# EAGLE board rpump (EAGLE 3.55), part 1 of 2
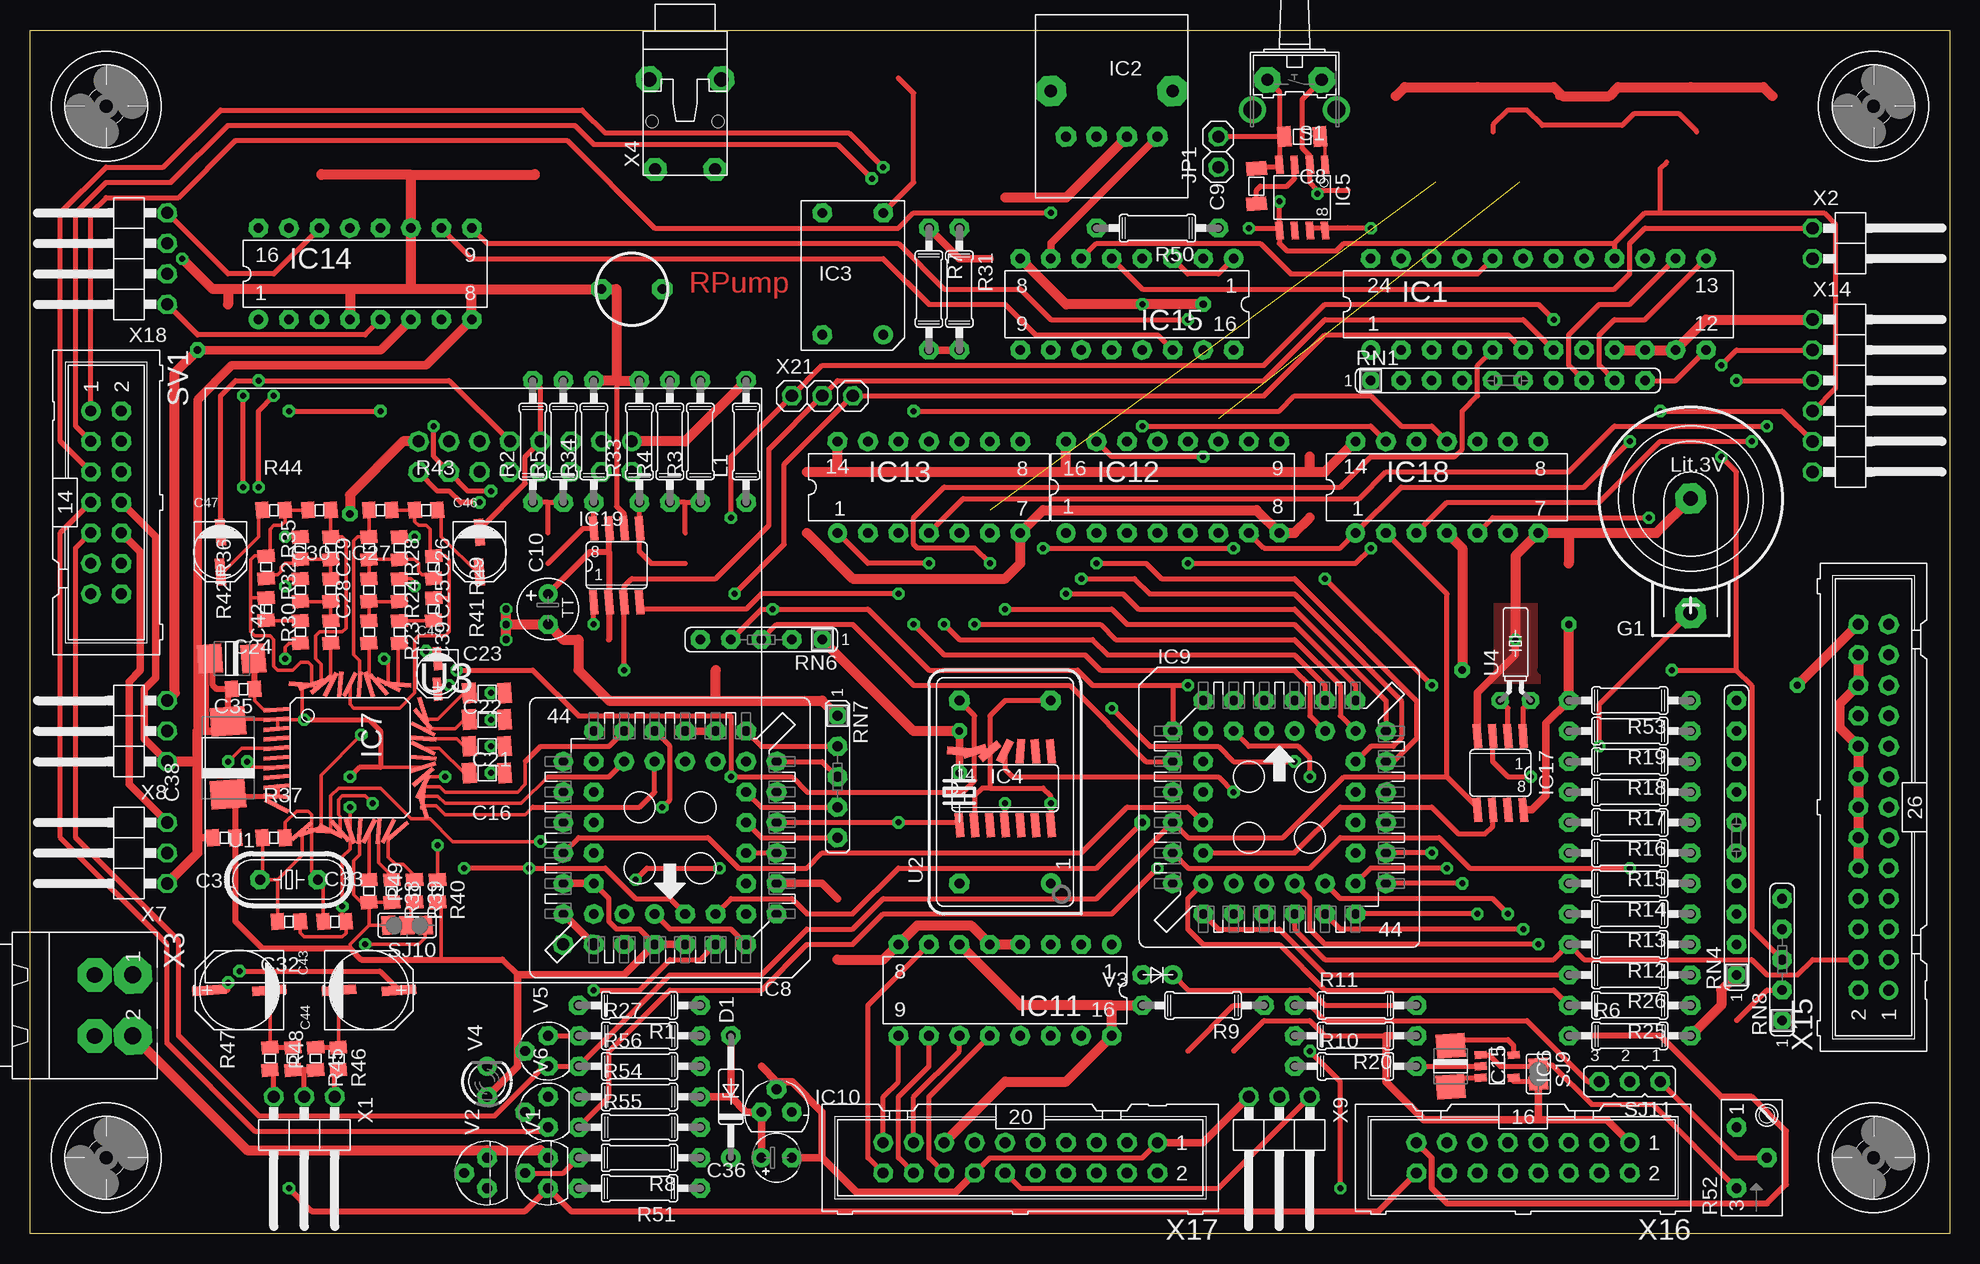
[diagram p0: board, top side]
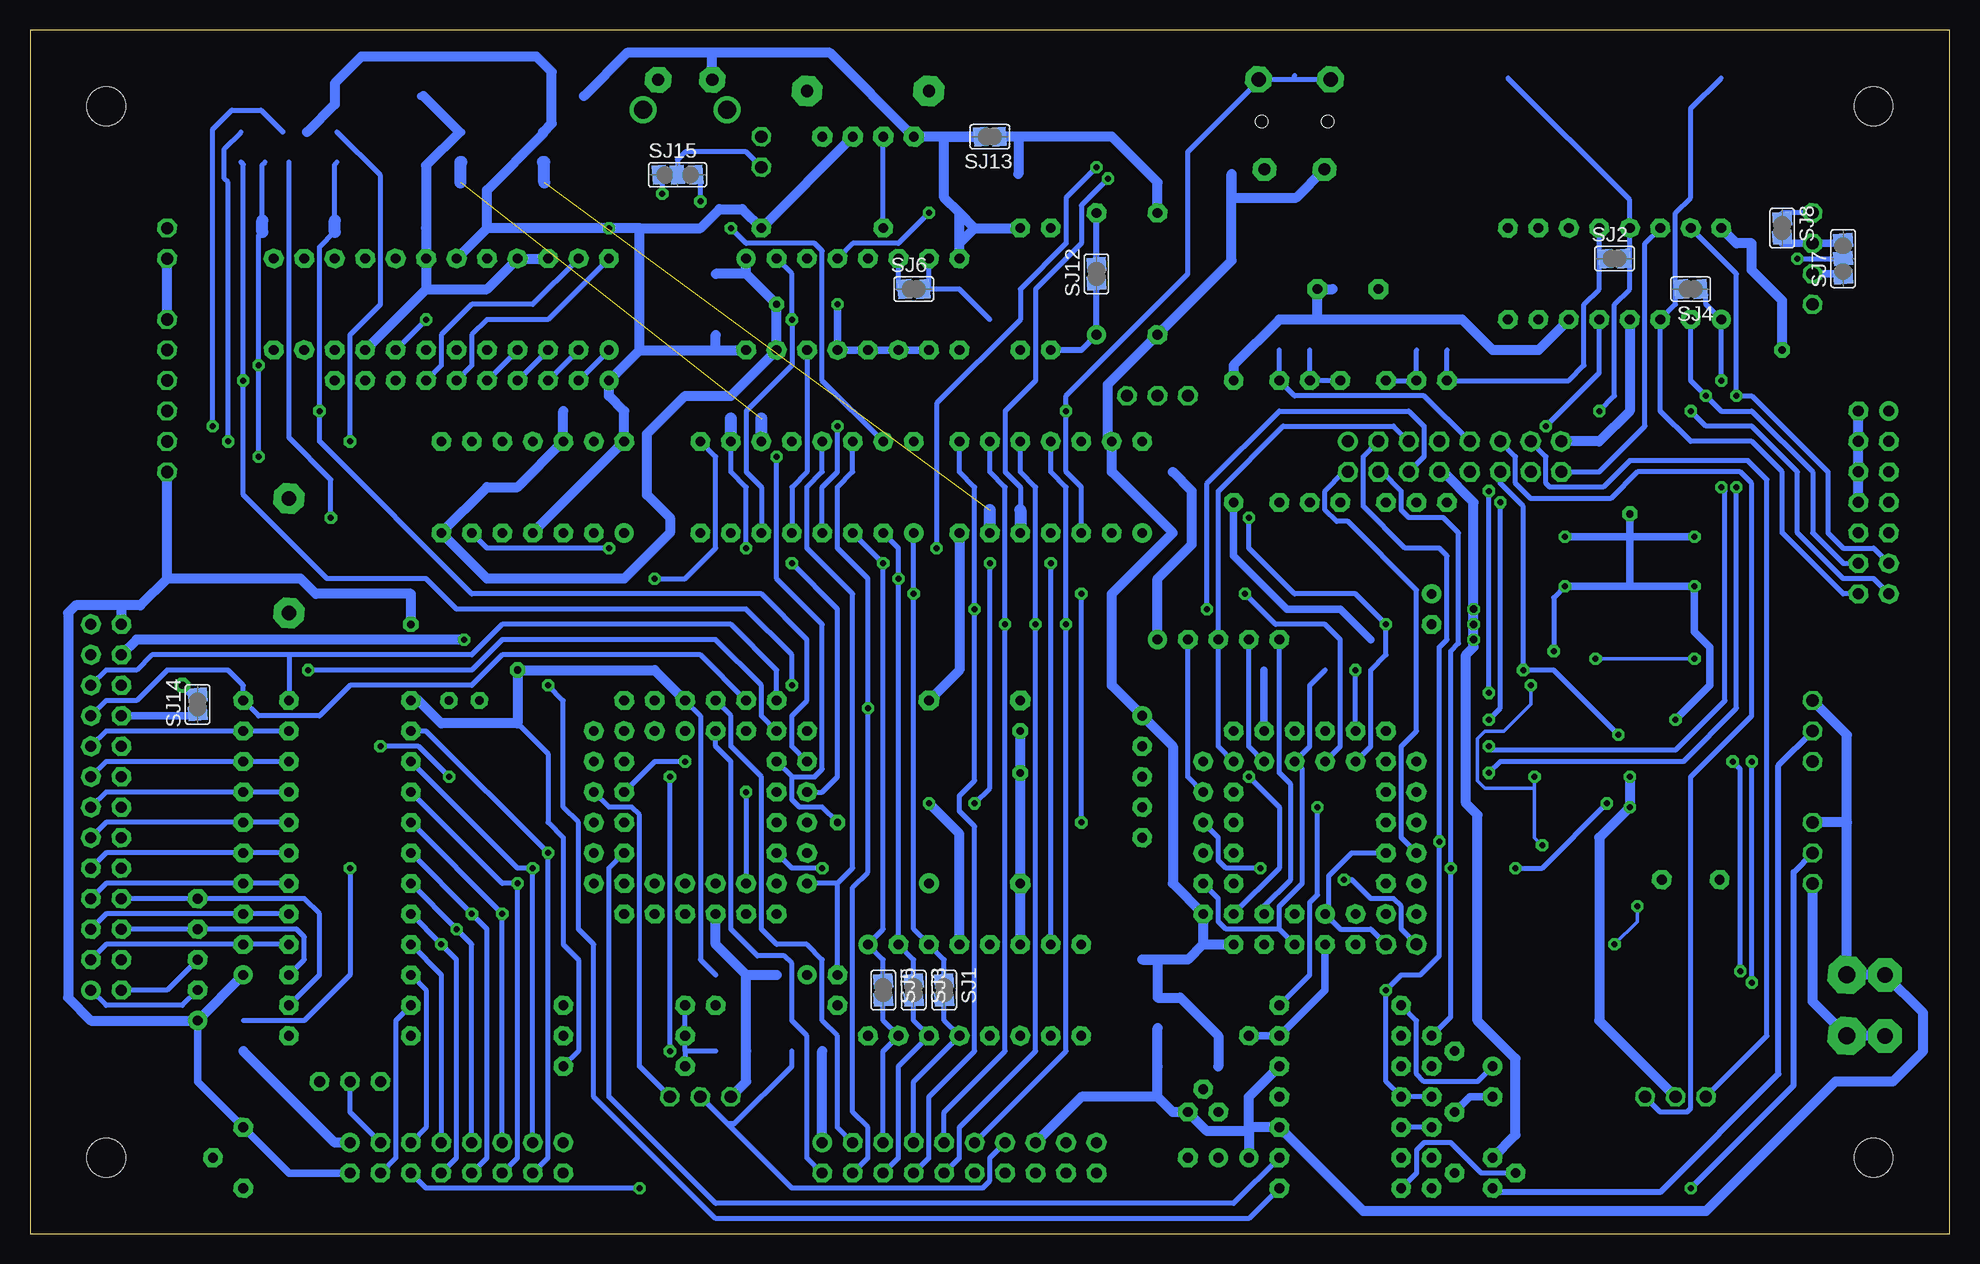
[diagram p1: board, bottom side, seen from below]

Size 160.02 x 100.33 mm. Coordinates in mm from the lower left corner, seen from the top.
Outline: 0,0 0,100.33 160.02,100.33 160.02,0 0,0
Copper layers used: Top, Bottom
tRestrict: 4 lines

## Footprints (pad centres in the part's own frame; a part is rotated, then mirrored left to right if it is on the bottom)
06 = smd 1.143 x 1.702 rotated 4.4:  1.473,0 | smd 1.143 x 1.702 rotated 4.3:  -1.473,0
2D5 = drill 0.813 pad 1.6 octagon:  -1.27,0 | drill 0.813 pad 1.6 round:  1.27,0
28 = smd 2.007 x 2.388 rotated 4.4:  1.702,0 | smd 2.007 x 2.388 rotated 4.3:  -1.702,0
05 = smd 1.092 x 1.397 rotated 4.4:  0.94,0 | smd 1.092 x 1.397 rotated 4.3:  -0.94,0
28' = smd 2.007 x 2.388 rotated 4.4:  1.802,0 | smd 2.007 x 2.388 rotated 4.3:  -1.802,0
2D4 = drill 0.813 pad 1.6 octagon:  -1.27,0 | drill 0.813 pad 1.6 round:  1.27,0
43 = smd 2.388 x 2.896 rotated 4.4:  3.048,0 | smd 2.388 x 2.896 rotated 4.3:  -3.048,0
C-D = smd 0.8 x 2.85 rotated 4.4:  0,2.5 | smd 0.8 x 2.85 rotated 4.3:  0,-2.5
C-A = smd 0.7 x 1.95 rotated 4.4:  0,1.27 | smd 0.7 x 1.95 rotated 4.3:  0,-1.27
C-B = smd 0.8 x 2.25 rotated 4.4:  0,1.64 | smd 0.8 x 2.25 rotated 4.3:  0,-1.67
35Z10 = drill 0.813 pad 1.6 round:  -5.08,0 | drill 0.813 pad 1.6 octagon:  5.08,0
1216 = drill 1.2 pad 2.54 octagon:  0,9.525;  0,0
L24-3 = drill 0.813 pad 1.6 round:  -13.97,-3.81 | drill 0.813 pad 1.6 octagon:  -11.43,-3.81;  -8.89,-3.81;  -6.35,-3.81;  -3.81,-3.81;  -1.27,-3.81;  1.27,-3.81;  3.81,-3.81;  6.35,-3.81;  8.89,-3.81;  11.43,-3.81;  13.97,-3.81;  13.97,3.81;  11.43,3.81;  8.89,3.81;  6.35,3.81;  3.81,3.81;  1.27,3.81;  -1.27,3.81;  -3.81,3.81;  -6.35,3.81;  -8.89,3.81;  -11.43,3.81;  -13.97,3.81
TX173 = drill 0.813 pad 1.676 octagon:  1.27,3.81;  3.81,3.81;  6.35,3.81;  8.89,3.81 | drill 1.016 pad 2.54 octagon:  0,0;  10.16,0
12545 = drill 0.813 pad 1.6 round:  2.54,-5.08 | drill 0.813 pad 1.6 octagon:  -2.54,-5.08;  2.54,5.08;  -2.54,5.08
14 = smd 0.66 x 2.032 rotated 4.3:  -3.81,-3.073;  1.27,3.073 | smd 0.66 x 2.032 rotated 94.3:  -3.81,3.073 | smd 0.66 x 2.032 rotated 4.4:  -2.54,-3.073 | smd 0.66 x 2.032 rotated 4.5:  -1.27,-3.073 | smd 0.66 x 2.032 rotated 71.8:  -2.54,3.073 | smd 0.66 x 2.032 rotated 49.3:  -1.27,3.073 | smd 0.66 x 2.032 rotated 4.6:  0,-3.073 | smd 0.66 x 2.032 rotated 26.8:  0,3.073 | smd 0.66 x 2.032 rotated 4.7:  1.27,-3.073;  2.54,-3.073 | smd 0.66 x 2.032 rotated 5:  2.54,3.073 | smd 0.66 x 2.032 rotated 4.8:  3.81,-3.073 | smd 0.66 x 2.032 rotated 4.9:  3.81,3.073
-8 = smd 0.61 x 1.524 rotated 4.3:  -1.27,-2.743 | smd 0.61 x 1.524 rotated 4.9:  -1.27,2.743 | smd 0.61 x 1.524 rotated 4.4:  0,-2.743 | smd 0.61 x 1.524 rotated 4.5:  1.27,-2.743 | smd 0.61 x 1.524 rotated 4.8:  0,2.743 | smd 0.61 x 1.524 rotated 4.7:  1.27,2.743;  2.54,2.743 | smd 0.61 x 1.524 rotated 4.6:  2.54,-2.743
T23-5 = smd 0.65 x 1 rotated 4.3:  -0.95,-1.33 | smd 0.65 x 1 rotated 4.4:  0,-1.33 | smd 0.65 x 1 rotated 4.5:  0.95,-1.33 | smd 0.65 x 1 rotated 4.6:  0.95,1.425 | smd 0.65 x 1 rotated 4.7:  -0.95,1.425
QFP44 = smd 0.35 x 2.2 rotated 4.3:  -4,-6.1;  3.2,-6.1 | smd 0.35 x 2.2 rotated 4.4:  -3.2,-6.1 | smd 0.35 x 2.2 rotated 4.5:  -2.4,-6.1;  -1.6,6.1 | smd 0.35 x 2.2 rotated 4.6:  -1.6,-6.1 | smd 0.35 x 2.2 rotated 4.7:  -0.8,-6.1;  0,-6.1 | smd 0.35 x 2.2 rotated 4.8:  0.8,-6.1 | smd 0.35 x 2.2 rotated 4.9:  1.6,-6.1 | smd 0.35 x 2.2 rotated 5:  2.4,-6.1 | smd 0.35 x 2.2 rotated 26.8:  4,-6.1 | smd 2.2 x 0.35 rotated 49.3:  6.1,-4 | smd 2.2 x 0.35 rotated 71.8:  6.1,-3.2 | smd 2.2 x 0.35 rotated 94.3:  6.1,-2.4 | smd 2.2 x 0.35 rotated 116.8:  6.1,-1.6 | smd 2.2 x 0.35 rotated 139.3:  6.1,-0.8 | smd 2.2 x 0.35 rotated 161.8:  6.1,0 | smd 2.2 x 0.35 rotated 184.3:  6.1,0.8 | smd 2.2 x 0.35 rotated 206.8:  6.1,1.6 | smd 2.2 x 0.35 rotated 4.4:  6.1,2.4 | smd 2.2 x 0.35 rotated 26.9:  6.1,3.2 | smd 2.2 x 0.35 rotated 49.4:  6.1,4 | smd 0.35 x 2.2 rotated 71.9:  4,6.1 | smd 0.35 x 2.2 rotated 94.4:  3.2,6.1 | smd 0.35 x 2.2 rotated 116.9:  2.4,6.1 | smd 0.35 x 2.2 rotated 139.4:  1.6,6.1 | smd 0.35 x 2.2 rotated 161.9:  0.8,6.1 | smd 0.35 x 2.2 rotated 184.4:  0,6.1 | smd 0.35 x 2.2 rotated 206.9:  -0.8,6.1 | smd 0.35 x 2.2 rotated 27:  -2.4,6.1 | smd 0.35 x 2.2 rotated 49.5:  -3.2,6.1 | smd 0.35 x 2.2 rotated 72:  -4,6.1 | smd 2.2 x 0.35 rotated 94.5:  -6.1,4 | smd 2.2 x 0.35 rotated 117:  -6.1,3.2 | smd 2.2 x 0.35 rotated 139.5:  -6.1,2.4 | smd 2.2 x 0.35 rotated 162:  -6.1,1.6 | smd 2.2 x 0.35 rotated 184.5:  -6.1,0.8 | smd 2.2 x 0.35 rotated 207:  -6.1,0 | smd 2.2 x 0.35 rotated 4.6:  -6.1,-0.8 | smd 2.2 x 0.35 rotated 27.1:  -6.1,-1.6 | smd 2.2 x 0.35 rotated 49.6:  -6.1,-2.4 | smd 2.2 x 0.35 rotated 72.1:  -6.1,-3.2 | smd 2.2 x 0.35 rotated 94.6:  -6.1,-4
4 = drill 0.813 pad 1.6 round:  1.27,6.35 | drill 0.813 pad 1.6 octagon:  -1.27,8.89;  -1.27,6.35;  -3.81,8.89;  -3.81,6.35;  -6.35,8.89;  -8.89,6.35;  -6.35,6.35;  -8.89,3.81;  -6.35,3.81;  -8.89,1.27;  -6.35,1.27;  -8.89,-1.27;  -6.35,-1.27;  -8.89,-3.81;  -6.35,-3.81;  -8.89,-6.35;  -6.35,-8.89;  -6.35,-6.35;  -3.81,-8.89;  -3.81,-6.35;  -1.27,-8.89;  -1.27,-6.35;  1.27,-8.89;  1.27,-6.35;  3.81,-8.89;  3.81,-6.35;  6.35,-8.89;  8.89,-6.35;  6.35,-6.35;  8.89,-3.81;  6.35,-3.81;  8.89,-1.27;  6.35,-1.27;  8.89,1.27;  6.35,1.27;  8.89,3.81;  6.35,3.81;  8.89,6.35;  6.35,8.89;  6.35,6.35;  3.81,8.89;  3.81,6.35;  1.27,8.89
92 = drill 0.813 pad 1.6 octagon:  -1.27,0;  0,1.905;  1.27,0
L16 = drill 0.813 pad 1.6 round:  -8.89,-3.81 | drill 0.813 pad 1.6 octagon:  -6.35,-3.81;  -3.81,-3.81;  -1.27,-3.81;  1.27,-3.81;  3.81,-3.81;  6.35,-3.81;  8.89,-3.81;  8.89,3.81;  6.35,3.81;  3.81,3.81;  1.27,3.81;  -1.27,3.81;  -3.81,3.81;  -6.35,3.81;  -8.89,3.81
L14 = drill 0.813 pad 1.6 round:  -7.62,-3.81 | drill 0.813 pad 1.6 octagon:  -5.08,-3.81;  -2.54,-3.81;  0,-3.81;  2.54,-3.81;  5.08,-3.81;  7.62,-3.81;  7.62,3.81;  5.08,3.81;  2.54,3.81;  0,3.81;  -2.54,3.81;  -5.08,3.81;  -7.62,3.81
08 = smd 0.66 x 2.032 rotated 4.3:  -1.905,-3.073 | smd 0.66 x 2.032 rotated 4.9:  -1.905,3.073 | smd 0.66 x 2.032 rotated 4.4:  -0.635,-3.073 | smd 0.66 x 2.032 rotated 4.5:  0.635,-3.073 | smd 0.66 x 2.032 rotated 4.8:  -0.635,3.073 | smd 0.66 x 2.032 rotated 4.7:  0.635,3.073;  1.905,3.073 | smd 0.66 x 2.032 rotated 4.6:  1.905,-3.073
02 = drill 1.016 pad 1.6 octagon:  -1.27,0;  1.27,0
07/10 = drill 0.813 pad 1.6 octagon:  -5.08,0;  5.08,0
4Y = drill 0.813 pad 1.6 octagon:  2.54,1.27;  -2.54,1.27;  0,-1.27
L10 = drill 0.813 pad 1.6 round:  -11.43,0 | drill 0.813 pad 1.6 octagon:  -8.89,0;  -6.35,0;  -3.81,0;  -1.27,0;  1.27,0;  3.81,0;  6.35,0;  8.89,0;  11.43,0
L5 = drill 0.813 pad 1.6 round:  -5.08,0 | drill 0.813 pad 1.6 octagon:  -2.54,0;  0,0;  2.54,0;  5.08,0
F-31XX = drill 1.016 pad 2.159 octagon:  -2.261,-1.245;  2.261,-1.245 | drill 1.499 pad 2.159 round:  -3.505,1.245;  3.505,1.245
 = smd 1.168 x 1.6 rotated 4.3:  -0.762,0 | smd 1.168 x 1.6 rotated 4.4:  0.762,0
2 = smd 1.168 x 1.6 rotated 4.3:  -1.524,0 | smd 1.168 x 1.6 rotated 4.4:  0,0 | smd 1.168 x 1.6 rotated 4.5:  1.524,0
2' = drill 0.914 pad 1.6 octagon:  -2.54,0;  0,0;  2.54,0
14' = drill 0.914 pad 1.6 round:  -7.62,-1.27 | drill 0.914 pad 1.6 octagon:  -7.62,1.27;  -5.08,-1.27;  -5.08,1.27;  -2.54,-1.27;  -2.54,1.27;  0,-1.27;  0,1.27;  2.54,-1.27;  2.54,1.27;  5.08,-1.27;  5.08,1.27;  7.62,-1.27;  7.62,1.27
49/S = drill 0.813 pad 1.6 octagon:  -2.413,0;  2.413,0
L14S = drill 0.813 pad 1.676 round:  -7.62,-3.81 | drill 0.813 pad 1.676 octagon:  7.62,-3.81;  7.62,3.81;  -7.62,3.81
P = drill 1 pad 1.651 round:  35.56,45.085 | drill 1 pad 1.651 octagon:  35.56,42.545;  33.02,45.085;  33.02,42.545;  30.48,45.085;  30.48,42.545;  27.94,45.085;  27.94,42.545;  25.4,45.085;  25.4,42.545;  22.86,45.085;  22.86,42.545;  20.32,45.085;  20.32,42.545;  17.78,45.085;  17.78,42.545;  29.845,3.175;  32.385,3.175
26H = drill 0.7 pad 1.422 octagon:  -1.27,0;  1.27,0
3,2S = hole 3.2: 0,0
92' = drill 0.813 pad 1.6 octagon:  1.27,0;  0,1.905;  -1.27,0
35-2,5 = drill 0.813 pad 1.6 round:  -1.27,0 | drill 0.813 pad 1.6 octagon:  1.27,0
D3 = drill 0.813 pad 1.6 octagon:  -1.27,0 | drill 0.813 pad 1.6 round:  1.27,0
T54E = drill 0.813 pad 1.6 octagon:  -1.27,0;  0,1.905;  1.27,0
03/90 = drill 1.016 pad 1.6 octagon:  -2.54,-3.81;  0,-3.81;  2.54,-3.81
02/90 = drill 1.016 pad 1.6 octagon:  -1.27,-3.81;  1.27,-3.81
TBA2 = drill 1.422 pad 3.15 octagon:  -2.54,5.08;  2.54,5.08
733962 = drill 1.2 pad 2.184 octagon:  3.5,3;  3.5,-3 | drill 1 pad 1.93 octagon:  -4,2.5;  -4,-2.5 | hole 1: 0,2.75; 0,-2.75
06/90 = drill 1.016 pad 1.6 octagon:  -6.35,-3.81;  -3.81,-3.81;  -1.27,-3.81;  1.27,-3.81;  3.81,-3.81;  6.35,-3.81
26 = drill 0.914 pad 1.6 round:  -15.24,-1.27 | drill 0.914 pad 1.6 octagon:  -15.24,1.27;  -12.7,-1.27;  -12.7,1.27;  -10.16,-1.27;  -10.16,1.27;  -7.62,-1.27;  -7.62,1.27;  -5.08,-1.27;  -5.08,1.27;  -2.54,-1.27;  -2.54,1.27;  0,-1.27;  0,1.27;  2.54,-1.27;  2.54,1.27;  5.08,-1.27;  5.08,1.27;  7.62,-1.27;  7.62,1.27;  10.16,-1.27;  10.16,1.27;  12.7,-1.27;  12.7,1.27;  15.24,-1.27;  15.24,1.27
16 = drill 0.914 pad 1.6 round:  -8.89,-1.27 | drill 0.914 pad 1.6 octagon:  -8.89,1.27;  -6.35,-1.27;  -6.35,1.27;  -3.81,-1.27;  -3.81,1.27;  -1.27,-1.27;  -1.27,1.27;  1.27,-1.27;  1.27,1.27;  3.81,-1.27;  3.81,1.27;  6.35,-1.27;  6.35,1.27;  8.89,-1.27;  8.89,1.27
20 = drill 0.914 pad 1.6 round:  -11.43,-1.27 | drill 0.914 pad 1.6 octagon:  -11.43,1.27;  -8.89,-1.27;  -8.89,1.27;  -6.35,-1.27;  -6.35,1.27;  -3.81,-1.27;  -3.81,1.27;  -1.27,-1.27;  -1.27,1.27;  1.27,-1.27;  1.27,1.27;  3.81,-1.27;  3.81,1.27;  6.35,-1.27;  6.35,1.27;  8.89,-1.27;  8.89,1.27;  11.43,-1.27;  11.43,1.27
04/90 = drill 1.016 pad 1.6 octagon:  -3.81,-3.81;  -1.27,-3.81;  1.27,-3.81;  3.81,-3.81
03 = drill 1.016 pad 1.6 octagon:  -2.54,0;  0,0;  2.54,0

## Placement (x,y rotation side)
C1  3.3u  [-2,5L]  43.18,55.88 90 top
C2  3.3u  [-2,5L]  54.61,55.88 90 top
C3  1n5  [2,5]  43.18,73.66 180 top
C4  1n5  [2,5]  54.61,73.66 0 top
C5  220u/10V  [-2,5L]  51.44,78.74 180 top
C6  100n  [5]  106.68,62.23 90 top
C7  100n  [5]  64.77,60.96 90 top
C8  1u  [06]  106.05,91.44 180 top
C9  1u  [06]  102.23,87.31 90 top
C10  22u  [2D5]  43.18,52.07 90 top
C11  100n  [2,5]  46.99,49.53 0 top
C12  100nF  [5]  80.01,78.74 270 top
C13  1n  [2,5]  142.24,16.51 90 top
C14  22u  [-2,5L]  96.52,15.24 180 top
C15  10u/1u*  [28]  118.43,13.97 270 top
C16  470n  [06]  38.1,38.42 180 top
C17  22u  [-2,5L]  102.87,15.24 180 top
C18  100u/10V  [-2,5L]  128.27,53.34 90 top
C19  100n  [5]  113.03,68.58 180 top
C20  100u/10V  [-2,5L]  66.04,17.14 90 top
C21  470n  [06]  38.1,42.86 180 top
C22  470n  [06]  38.1,40.64 0 top
C23  470n  [06]  38.1,45.09 0 top
C24  10n  [05]  17.78,45.4 0 top
C25  560p  [05]  30.8,53.66 270 top
C26  270p  [05]  30.8,57.15 270 top
C27  100p  [05]  29.21,60.33 180 top
C28  560p  [05]  22.54,53.66 270 top
C29  270p  [05]  22.54,57.15 270 top
C30  100p  [05]  24.13,60.33 180 top
C31  1n  [05]  16.19,33.02 180 top
C32  22p  [05]  21.59,26.04 180 top
C33  22p  [05]  25.4,26.04 0 top
C34  1u/1206  [5]  100.33,21.59 0 top
C35  3u3  [28']  16.83,47.94 180 top
C36  10u  [2D4]  62.23,6.35 180 top
C37  1u  [5]  63.5,13.97 0 top
C38  22u  [43]  16.51,39.69 90 top
C39  1n  [05]  30.8,50.16 270 top
C40  100nF  [5]  54.61,46.99 180 top
C41  100nF  [5]  67.31,25.4 90 top
C42  1n  [05]  22.54,50.16 90 top
C43  150u  [C-D]  17.46,20.32 270 top
C44  150u  [C-D]  28.26,20.32 90 top
C45  2u2  [C-A]  33.97,46.67 0 top
C46  1u  [C-B]  37.47,56.83 0 top
C47  1u  [C-B]  15.88,56.83 0 top
C48  100n  [5]  124.46,83.82 180 top
C49  100n  [5]  16.51,80.01 90 top
C50  100n  [5]  102.87,77.47 270 top
C51  100n  [5]  81.28,88.9 270 top
D1  ZPD1,4  [35Z10]  58.42,11.43 90 top
G1  3V Lithium  [1216]  138.43,61.28 180 top
IC1  CS8402  [L24-3]  125.73,77.47 0 top
IC2  TOTX173  [TX173]  95.25,95.25 180 top
IC3  6712545  [12545]  68.58,80.01 0 top
IC4  74393  [14]  81.28,37.15 0 top
IC5  TL7705A  [-8]  106.68,86.36 180 top
IC6  MAX828/MAX870*  [T23-5]  122.24,13.97 270 top
IC7  DAC3550A  [QFP44]  26.67,39.69 270 top
IC8  MAS3507D  [4]  53.34,33.02 180 top
IC9  90S8515  [4]  104.14,35.56 0 top
IC10  LE33CZ  [92]  62.23,10.16 0 top
IC11  74138  [L16]  81.28,20.32 180 top
IC12  74259  [L16]  95.25,62.23 0 top
IC13  74242  [L14]  74.93,62.23 0 top
IC14  MAX4618  [L16]  27.94,80.01 0 top
IC15  74153  [L16]  91.44,77.47 180 top
IC17  DS1307  [08]  122.56,38.42 180 top
IC18  74126  [L14]  118.11,62.23 0 top
IC19  CS4334  [08]  48.89,55.72 0 top
JP1  ext_Reset  [02]  99.06,90.17 90 top
L1  100uH  [07/10]  59.69,66.04 90 top
R1  1k  [07/10]  50.8,19.05 180 top
R2  560R  [07/10]  41.91,66.04 90 top
R3  560R  [07/10]  55.88,66.04 90 top
R4  10k  [07/10]  53.34,66.04 90 top
R5  10k  [07/10]  44.45,66.04 90 top
R6  15R  [07/10]  133.35,16.51 0 top
R7  375R  [07/10]  74.93,78.74 270 top
R8  4k7  [07/10]  50.8,6.35 180 top
R9  15R  [07/10]  97.79,19.05 180 top
R10  R  [07/10]  110.49,13.97 0 top
R11  1k  [07/10]  110.49,19.05 0 top
R12  680R  [07/10]  133.35,24.13 180 top
R13  680R  [07/10]  133.35,26.67 180 top
R14  680R  [07/10]  133.35,29.21 180 top
R15  680R  [07/10]  133.35,31.75 180 top
R16  680R  [07/10]  133.35,34.29 180 top
R17  680R  [07/10]  133.35,36.83 180 top
R18  680R  [07/10]  133.35,39.37 180 top
R19  680R  [07/10]  133.35,41.91 180 top
R20  R  [07/10]  110.49,16.51 180 top
R21  10k  [06']  109.86,85.41 270 top
R23  7k5  [05]  28.26,50.16 270 top
R24  7k5  [05]  28.26,53.66 270 top
R25  680R  [07/10]  133.35,19.05 180 top
R26  680R  [07/10]  133.35,21.59 180 top
R27  2k  [07/10]  50.8,16.51 0 top
R28  7k5  [05]  28.26,57.15 270 top
R29  15k  [05]  33.66,55.56 270 top
R30  7k5  [05]  25.08,50.16 90 top
R31  91R  [07/10]  77.47,78.74 270 top
R32  7k5  [05]  25.08,53.66 90 top
R33  267k  [07/10]  50.8,66.04 90 top
R34  267k  [07/10]  46.99,66.04 90 top
R35  7k5  [05]  25.08,57.15 90 top
R36  15k  [05]  19.68,55.56 90 top
R37  1M  [05]  20.32,33.02 0 top
R38  10k  [05]  28.26,28.57 270 top
R39  10k  [05]  30.16,28.57 270 top
R40  10k  [05]  32.07,28.57 270 top
R41  22k  [05]  33.66,52.07 270 top
R42  22k  [05]  19.68,52.07 90 top
R43  680  [05]  33.02,60.33 0 top
R44  680  [05]  20.32,60.33 0 top
R45  1k5  [05]  21.91,14.61 270 top
R46  1k5  [05]  23.81,14.61 270 top
R47  47  [05]  20,14.61 90 top
R48  47  [05]  25.72,14.61 90 top
R49  10k  [05]  33.97,28.57 90 top
R50  8k2  [07/10]  93.98,83.82 180 top
R51  4k7  [07/10]  50.8,3.81 180 top
R52  10k  [4Y]  143.51,6.35 90 top
R53  10k  [07/10]  133.35,44.45 180 top
R54  2k  [07/10]  50.8,11.43 0 top
R55  4,7k  [07/10]  50.8,8.89 0 top
R56  4,7k  [07/10]  50.8,13.97 0 top
RN1  10k  [L10]  123.19,71.12 0 top
RN4  10k  [L10]  142.24,33.02 90 top
RN6  10k  [L5]  60.96,49.53 180 top
RN7  10k  [L5]  67.31,38.1 270 top
RN8  1k  [L5]  146.05,22.86 90 top
S1  Reset  [F-31XX]  105.41,94.93 180 top
SJ1  Tast4  []  83.82,20.32 270 bottom
SJ2  SkipMUX_L  []  27.94,81.28 0 bottom
SJ3  Tast5  []  86.36,20.32 270 bottom
SJ4  SkipMUX_R  []  21.59,78.74 180 bottom
SJ5  Tast6  []  88.9,20.32 270 bottom
SJ6  SkipMUX_D  []  86.36,78.74 0 bottom
SJ7  GND  [2]  8.89,81.28 90 bottom
SJ8  CD_Sig2  []  13.97,83.82 270 bottom
SJ9  Max present?  []  125.73,13.34 270 top
SJ10  DEE  [2]  31.43,25.72 180 top
SJ11  Kontr  [2']  133.35,12.7 180 top
SJ12  SkipTra1  []  71.12,80.01 90 bottom
SJ13  SkipTra2  []  80.01,91.44 180 bottom
SJ14  VCC_LPT  []  146.05,44.13 90 bottom
SJ15  Reset  [2]  106.05,88.27 0 bottom
SV1  ML14E  [14']  6.35,60.96 270 top
U1  14.725MHz  [49/S]  21.59,29.53 0 top
U2  14.7456MHz  [L14S]  81.28,36.83 90 top
U3  DSP  [P]  14.61,20.95 0 top
U4  32kHz  [26H]  123.83,44.45 0 top
U$2  [3,2S]  6.35,93.98 0 top
U$3  [3,2S]  6.35,6.35 0 top
U$4  [3,2S]  153.67,93.98 0 top
U$5  [3,2S]  153.67,6.35 0 top
U$7  [TB2]  not placed on the board
V1  BC337  [92']  43.18,5.08 90 top
V2  BC337  [92']  38.1,5.08 90 top
V3  1N4148  [35-2,5]  93.98,21.59 180 top
V4  LED 2mA  [D3]  38.1,12.7 90 top
V5  BSN10A  [T54E]  43.18,15.24 90 top
V6  BSN10A  [T54E]  43.18,10.16 90 top
X1  Phones  [03/90]  22.86,7.62 180 top
X2  CD SPDIF IN  [02/90]  152.4,82.55 270 top
X3  MSTBA2  [TBA2]  3.49,19.05 270 top
X4  Sony-Bus  [733962]  54.61,92.71 90 top
X5  MiniDIN-6  [NI-6]  120.65,100.33 0 top
X6  MiniDIN-9  [NI-9N]  138.43,100.33 0 top
X7  Power_1  [03/90]  7.62,31.75 90 top
X8  Power_2  [03/90]  7.62,41.91 90 top
X9  IR_aux  [03/90]  104.14,7.62 180 top
X10  AnalogOut R  [TOR1]  36.83,100.33 0 top
X11  AnalogOut L  [TOR1]  19.05,100.33 0 top
X12  S/P-DIF  [TOR1]  72.39,100.33 0 top
X13  Grundig-Bus  [TOR1]  54.61,100.33 0 top
X14  PonyProgIF  [06/90]  152.4,69.85 270 top
X15  LPT-Conn  [26]  153.67,35.56 90 top
X16  Display  [16]  124.46,6.35 180 top
X17  Keypad  [20]  82.55,6.35 180 top
X18  CD Audio IN  [04/90]  7.62,81.28 90 top
X21  I2S  [03]  66.04,69.85 0 top

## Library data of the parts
C1-C7 C11-C14 C17-C20 C24-C35 C37-C51 R21 R23 R24 R28-R30 R32 R35-R49 = DISCRETE
C8 C9 = cap
C10 C36 = CAP-TANT
C15 C16 C21-C23 = SMD
D1 V3 = DIODE
G1 = BATTERY
IC1 = DIL
IC2 IC9 = mp3
IC3 = rpump2LB
IC4 = 74XXSMD
IC5 IC17 IC19 = maxim
IC6 = 74xxdin
IC7 = micronas
IC8 = PLCCPACK
IC10 = V-REG
IC11-IC15 IC18 = 74XX
JP1 X1 X2 X7-X9 X14 X18 X21 = PINHEAD
L1 R1-R20 R25-R27 R31 R33 R34 R50 R51 R53-R56 = r
R52 = TRIMPOT
RN1 RN4 RN6-RN8 = r-sil
S1 = KEYOMRON
SJ1-SJ10 SJ12-SJ15 = JUMPER
SJ11 = JUMPS
SV1 X15-X17 = CON-ML
U1 = QUARTZ
U2 U4 = quartz
U3 = SPECIAL
U$2-U$5 = HOLES
U$7 X3 = PHO508E
V1 V2 V5 V6 = TRANS-SM
V4 = LED
X4-X6 X10-X13 = HIRSCHM

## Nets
+3,3V: C31. C36. C38. C40. C41. D1. IC7. IC8. IC10. R27. R38. R39. R49. R54. SJ10. V4. V5. V6.
-5V: IC6. R52. SJ9.
/RES: IC1. IC5. IC8. IC9. IC12. RN6. SJ15. X6. X14.
AUX1L: C21. IC14. SJ8. U3. X18.
AUX1R: C23. IC14. U3. X18.
AUX2L: C16. IC14. SV1.
AUX2R: C22. IC14. SV1.
BUSY: IC9. R53. X15.
CLOCK: IC4. IC9.
CTRL0: R26. RN8. X15.
CTRL1: R25. RN8. X15.
D0: IC9. R12. X15. X16.
D1: IC9. R13. X16.
D2: IC9. R14. X16.
D3: IC9. R15. X16.
D4: IC9. R16. X16.
D5: IC9. R17. X16.
D6: IC9. R18. X16.
D7: IC9. R19. X16.
DCF: IC13. X5. X6.
DEMAND: IC8. IC9. U3.
DIG_IN: IC13. SV1.
DIG_OUT: IC12. SV1.
DIGIGND: IC3. SJ13. X12.
DREH0: IC9. X17.
DREH1: IC9. X17.
GND: C3. C4. C5. C6. C7. C8. C9. C10. C11. C13. C14. C17. C18. C19. C20. C24. C25. C26. C28. C29. C31. C32. C33. C34. C35. C36. C37. C38. C40. C41. C45. C48. C49. C50. C51. G1. IC1. IC2. IC3. IC4. IC5. IC6. IC7. IC8. IC9. IC10. IC11. IC12. IC13. IC14. IC15. IC17. IC18. IC19. JP1. R4. R5. R20. R31. R33. R34. R45. R46. RN7. S1. SJ7. SJ9. SJ10. SJ13. SV1. U2. U3. V1. V2. X1. X2. X3. X4. X5. X6. X7. X8. X9. X10. X11. X13. X14. X15. X16. X17.
I2CC: IC9. IC17. R55. SV1. V6.
I2CD: IC9. IC17. IC18. R56. SV1. V5.
I_SEL0: IC12. IC14. IC15.
I_SEL1: IC12. IC14. IC15.
INT: IC9. RN4. X15.
IR: IC9. X9. X17.
KONTR: IC9. IC12. V3.
LCD_SEL: IC9. X16.
LED+: R6. X16.
LED-: V1. X7. X16.
LEFT: IC14. SJ2. SV1. X10.
LIGHT: IC9. R8.
MCL: IC4. IC8. IC19.
MCL/4: IC1. IC4.
N$1: IC1. RN1.
N$2: R11. V3.
N$3: SJ11. X16.
N$4: R8. V1.
N$5: R1. V4.
N$6: SJ14. X15.
N$7: C10. C11. IC19. L1.
N$8: C1. IC19. R34.
N$9: C2. IC19. R33.
N$10: IC2. R50.
N$11: C1. R2. R5.
N$12: G1. IC17.
N$13: IC8.
N$14: R52. SJ11.
N$15: C2. R3. R4.
N$16: C12. R7.
N$17: R51. V2.
N$18: C15. IC6.
N$19: V2. X8.
N$20: C15. IC6.
N$21: IC1. RN1.
N$22: C8. IC5.
N$23: SJ7. SJ8. X18.
N$24: C9. IC5.
N$25: SJ7. X18.
N$26: IC1. IC15. SJ6.
N$27: IC13. X5.
N$28: IC3. SJ12. X12.
N$29: IC1. RN1.
N$30: IC1. RN1.
N$31: IC1. RN1.
N$32: IC17. U4.
N$33: IC1. RN1.
N$34: IC1. RN1.
N$35: IC1. RN1.
N$36: IC12. X5.
N$37: JP1. SJ15.
N$40: C16. IC7.
N$42: C12. IC2. IC15. SJ6.
N$43: IC3. R7. R31. SJ12.
N$44: C21. IC7.
N$45: C22. IC7.
N$46: C23. IC7.
N$47: C24. C35. IC7.
N$48: IC7. R38.
N$49: IC7. R39.
N$50: IC7. R40.
N$56: C32. IC7. R37. U1.
N$57: C33. IC7. R37. U1.
N$58: IC7. R23.
N$59: C25. R23. R24.
N$60: C26. R24. R28. R29.
N$61: IC7. R30.
N$62: C28. R30. R32.
N$63: C29. R32. R35. R36.
N$64: C27. IC7. R28.
N$65: C30. IC7. R35.
N$66: C27. IC7. R29. R41. R43.
N$67: C30. IC7. R36. R42. R44.
N$68: C39. IC7.
N$69: C39. R41.
N$70: C42. IC7.
N$71: C42. R42.
N$72: R40. SJ10.
N$73: C46. R43.
N$74: C47. R44.
N$77: IC15. X2.
N$78: C43. IC7.
N$80: C44. IC7.
N$81: C43. R45. R47.
N$82: C44. R46. R48.
N$83: C45. IC7. R49.
N$87: IC1. RN1.
N$90: IC12. IC18.
N$98: IC17. U4.
NC: IC14.
OUT_L: C3. C46. IC14. R2. SJ2. U3.
OUT_R: C4. C47. IC14. R3. SJ4. U3.
PD0: R12. RN4. X15.
PD1: R13. RN4. X15.
PD2: R14. RN4. X15.
PD3: R15. RN4. X15.
PD4: R16. RN4. X15.
PD5: R17. RN4. X15.
PD6: R18. RN4. X15.
PD7: R19. RN4. X15.
PH_L: R47. U3. X1.
PH_R: R48. U3. X1.
PI0: IC8. RN7.
PI1: IC8. RN6.
PI2: IC8. RN7.
PI3: IC8. RN7.
PI4: IC8. RN7.
PI8: IC8. R1.
RES_MAN: IC5. R21. S1. SJ15.
RIGHT: IC14. SJ4. SV1. X11.
ROW3: IC11. X17.
ROW4: IC11. X17.
ROW5: IC11. X17.
ROW6: IC11. X17.
ROW7: IC11. IC13. X17.
RX: IC9. IC18.
RXD: IC18. X6.
SCHALT2: IC12. R51.
SCL3: IC7. IC8. R54. U3. V6.
SCLK: IC8. IC9. RN6. U3. X6. X14.
SDA3: IC7. IC8. R27. U3. V5.
SDATA: IC8. IC9. RN6. U3. X6. X14.
SEL0: IC9. R26. X16.
SEL1: IC9. R25. X16.
SOC: IC1. IC7. IC8. X21.
SOD: IC1. IC7. IC8. IC19. X21.
SOI: IC1. IC7. IC8. IC19. X21.
SONY: IC13. IC18. X4. X13.
SPDIFAUX: IC15. SV1.
SREAD: IC9. RN8. X6. X14. X15.
STROBE: C13. IC9. RN8. X15.
T4/R0: IC11. SJ1. X17.
T5/R1: IC11. SJ3. X17.
T6/R2: IC11. SJ5. X17.
TAKT: IC4. IC7. IC8. U2. U3.
TAST0: IC9. IC13. X17.
TAST1: IC9. IC13. X17.
TAST2: IC9. IC13. X17.
TAST3: IC9. IC13. X17.
TAST4: IC9. IC11. IC12. SJ1.
TAST5: IC9. IC11. IC12. SJ3.
TAST6: IC9. IC11. IC12. SJ5.
TAST7: IC9. IC12. X17.
TRANSMIT: IC12. IC18. X6.
TXD: IC18. X6.
VCC: C5. C6. C7. C18. C19. C20. C34. C37. C48. C49. C50. C51. D1. IC1. IC2. IC4. IC5. IC6. IC9. IC10. IC11. IC12. IC13. IC14. IC15. IC17. IC18. L1. R6. R9. R10. R21. R50. R52. R53. R55. R56. RN1. RN4. RN6. RN8. SJ14. SV1. U2. U3. X3. X5. X6. X7. X8. X14. X15. X16. X17.
VCONTR: C17. R10. R11. R20. SJ11.
VIR: C14. R9. X9. X17.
